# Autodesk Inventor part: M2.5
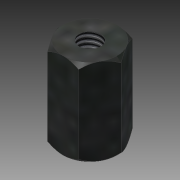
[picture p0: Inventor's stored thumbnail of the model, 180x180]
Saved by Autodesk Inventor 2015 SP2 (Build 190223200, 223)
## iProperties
Created: 2012-08
Part Number: M2.5
Material: Stahl
Document SubType Name: Modeling
Designer: rYan
Mass: 3.36246 g
Surface Area: 5.74911 cm^2
Volume: 0.428339 cm^3
Density: 7.85 g/cm^3
Appearance: Platte
Author: rYan
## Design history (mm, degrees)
derived "Abstandsbolzen Typ A.ipt"
feature "Volumenkörper1::Abstandsbolzen Typ A.ipt"
tag "Bezeichnung1"
node "Volumenkörper1"
other parameters: "SW" = 5, "L" = 8, "d2" = 0, "d16" = 45 deg
